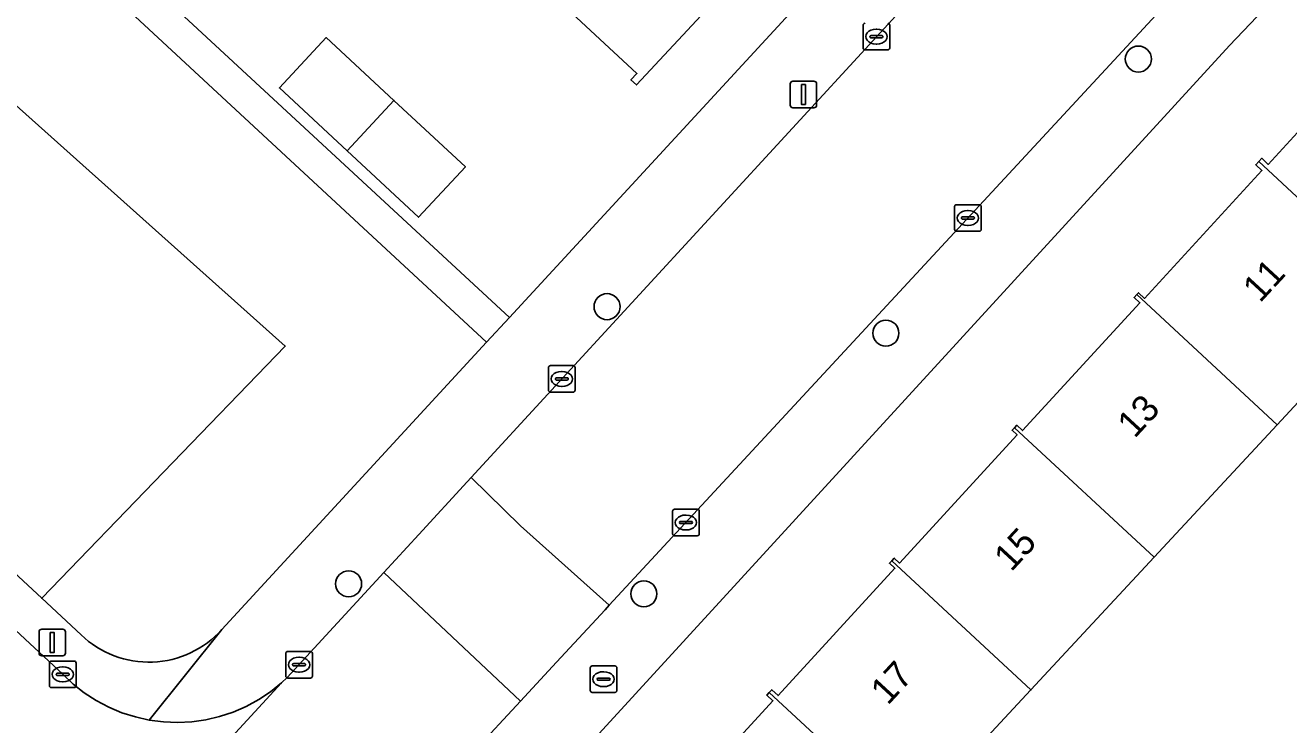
# Model space of a CAD drawing. Extents: x 159217 to 160349, y 381246 to 382172.
# Drawn here: x 159886.39 to 159933.87, y 381674.16 to 381700.45 of the extents above; entities that cross this region are included whole.
import ezdxf

# ---------------------------------------------------------------- set-up
doc = ezdxf.new("R2010")
doc.units = 0
for name, color, linetype in [('IMGEO_Boom', 7, 'Continuous'), ('IMGEO_Brandkraan', 7, 'Continuous'), ('IMGEO_Erf', 7, 'Continuous'), ('IMGEO_Groenvoorziening', 7, 'Continuous'), ('IMGEO_Kolk', 7, 'Continuous'), ('IMGEO_Lichtmast', 7, 'Continuous'), ('IMGEO_Pand', 7, 'Continuous'), ('IMGEO_Pand_nummerreeks', 7, 'Continuous'), ('IMGEO_Rijbaan_lokaal_open', 7, 'Continuous'), ('IMGEO_Voetpad_open', 7, 'Continuous')]:
    doc.layers.add(name, color=color, linetype=linetype)

msp = doc.modelspace()

# ---------------------------------------------------------------- linework, layer by layer
at = {"layer": 'IMGEO_Boom'}
for centre in [(159928.216, 381699.184), (159908.251, 381689.874), (159918.73, 381688.877), (159898.542, 381679.454), (159909.636, 381679.078)]:
    msp.add_circle(centre, 0.489, dxfattribs=at)
at = {"layer": 'IMGEO_Brandkraan'}
for p, q in [((159907.621, 381675.443), (159907.621, 381676.295)), ((159907.696, 381676.369), (159908.548, 381676.369)), ((159908.109, 381676.149), (159908.134, 381676.149)), ((159908.622, 381676.295), (159908.622, 381675.443)), ((159907.88, 381675.863), (159907.88, 381675.875)), ((159908.318, 381675.826), (159907.92, 381675.826)), ((159907.923, 381675.912), (159908.321, 381675.912)), ((159908.364, 381675.875), (159908.364, 381675.863)), ((159908.548, 381675.369), (159907.696, 381675.369)), ((159908.132, 381675.589), (159908.107, 381675.589))]:
    msp.add_line(p, q, dxfattribs=at)
for points in [[(159907.621, 381675.443), (159907.621, 381676.295)], [(159907.696, 381676.369), (159908.548, 381676.369)], [(159908.622, 381676.295), (159908.622, 381675.443)], [(159908.548, 381675.369), (159907.696, 381675.369)]]:
    msp.add_lwpolyline(points, dxfattribs=at)
for centre, radius, start, end in [((159907.698, 381676.293), 0.0765, 91.552, 178.448), ((159907.698, 381676.293), 0.0765, 91.552, 178.448), ((159908.546, 381676.293), 0.0765, 1.552, 88.448), ((159908.546, 381676.293), 0.0765, 1.552, 88.448), ((159907.92, 381675.872), 0.0403, 85.8775, 175.7526), ((159907.917, 381675.862), 0.0366, 178.938, 274.7102), ((159908.321, 381675.869), 0.043, 264.8664, 352.4533), ((159908.325, 381675.874), 0.0386, 1.7309, 96.639), ((159907.698, 381675.445), 0.0765, 181.552, 268.448), ((159907.698, 381675.445), 0.0765, 181.552, 268.448), ((159908.546, 381675.445), 0.0765, 271.552, 358.448), ((159908.546, 381675.445), 0.0765, 271.552, 358.448)]:
    msp.add_arc(centre, radius, start, end, dxfattribs=at)
for centre, major_axis, ratio, start_param, end_param in [((159908.108, 381675.869), (-0.387, 0.002), 0.722429, 4.712389, 7.853982), ((159908.133, 381675.869), (-0.39, 0.002), 0.717154, 1.570796, 4.712389)]:
    msp.add_ellipse(centre, major_axis=major_axis, ratio=ratio, start_param=start_param, end_param=end_param, dxfattribs=at)
at = {"layer": 'IMGEO_Erf'}
for points in [[(159847.871, 381715.151), (159862.984, 381701.234), (159876.444, 381715.527), (159904.584, 381689.472), (159917.923, 381703.96), (159873.098, 381745.66)], [(159955.211, 381724.431), (159931.645, 381699.69), (159903.156, 381668.59)], [(159910.098, 381670.269), (159914.487, 381675.06), (159914.255, 381675.272), (159914.347, 381675.373), (159914.439, 381675.474), (159914.68, 381675.253), (159919.066, 381680.041), (159918.863, 381680.227), (159918.951, 381680.323), (159919.041, 381680.421), (159919.244, 381680.235), (159923.662, 381685.057), (159923.474, 381685.229), (159923.56, 381685.322), (159923.645, 381685.415), (159923.866, 381685.212), (159928.274, 381690.024), (159928.057, 381690.222), (159928.155, 381690.33), (159928.217, 381690.398), (159928.45, 381690.187), (159932.857, 381694.998), (159932.628, 381695.208), (159932.74, 381695.33), (159932.852, 381695.452), (159933.1, 381695.225), (159937.498, 381700.026)], [(159938.045, 381690.407), (159933.431, 381685.435), (159928.807, 381680.452), (159924.182, 381675.468), (159919.583, 381670.513)]]:
    msp.add_lwpolyline(points, dxfattribs=at)
for points in [[(159904.989, 381702.728), (159900.602, 381706.809), (159896.139, 381710.961), (159891.711, 381715.08), (159887.361, 381719.127), (159883.151, 381723.044), (159882.945, 381722.822), (159882.765, 381722.99), (159884.38, 381724.726), (159887.785, 381728.386), (159887.946, 381728.236), (159887.703, 381727.975), (159891.932, 381724.04), (159896.283, 381719.994), (159900.711, 381715.874), (159905.173, 381711.722), (159909.56, 381707.641), (159913.942, 381703.565), (159914.075, 381703.708), (159914.398, 381703.634), (159909.356, 381698.214), (159909.152, 381698.404), (159909.377, 381698.646), (159905.716, 381702.051)], [(159897.7, 381699.993), (159900.243, 381697.627), (159902.928, 381695.129), (159901.167, 381693.236), (159898.482, 381695.734), (159895.939, 381698.1)]]:
    msp.add_lwpolyline(points, close=True, dxfattribs=at)
at = {"layer": 'IMGEO_Groenvoorziening'}
for points in [[(159903.728, 381688.543), (159877.305, 381713.035), (159875.829, 381712.89), (159864.051, 381700.243), (159868.505, 381696.104), (159876.898, 381705.634), (159896.16, 381688.389), (159887.008, 381678.914), (159888.492, 381677.536)], [(159893.779, 381677.737), (159903.728, 381688.543)]]:
    msp.add_lwpolyline(points, dxfattribs=at)
msp.add_lwpolyline([(159876.898, 381705.634), (159868.505, 381696.104), (159887.008, 381678.914), (159896.16, 381688.389)], close=True, dxfattribs=at)
msp.add_arc((159891.039, 381680.178), 3.67, 226.0485, 318.3059, dxfattribs=at)
at = {"layer": 'IMGEO_Kolk'}
for p, q in [((159917.873, 381699.602), (159917.873, 381700.454)), ((159918.874, 381700.454), (159918.874, 381699.602)), ((159918.132, 381700.022), (159918.132, 381700.034)), ((159918.57, 381699.985), (159918.172, 381699.985)), ((159918.175, 381700.071), (159918.573, 381700.071)), ((159918.361, 381700.308), (159918.386, 381700.308)), ((159918.616, 381700.034), (159918.616, 381700.022)), ((159918.8, 381699.528), (159917.948, 381699.528)), ((159918.384, 381699.748), (159918.359, 381699.748)), ((159921.387, 381693.708), (159922.239, 381693.708)), ((159921.312, 381692.782), (159921.312, 381693.634)), ((159921.614, 381693.251), (159922.012, 381693.251)), ((159921.8, 381693.488), (159921.825, 381693.488)), ((159922.313, 381693.634), (159922.313, 381692.782)), ((159921.571, 381693.202), (159921.571, 381693.214)), ((159922.009, 381693.165), (159921.611, 381693.165)), ((159921.823, 381692.928), (159921.798, 381692.928)), ((159922.055, 381693.214), (159922.055, 381693.202)), ((159922.239, 381692.708), (159921.387, 381692.708)), ((159906.051, 381686.732), (159906.051, 381687.584)), ((159906.126, 381687.658), (159906.978, 381687.658)), ((159907.052, 381687.584), (159907.052, 381686.732)), ((159906.31, 381687.152), (159906.31, 381687.164)), ((159906.748, 381687.115), (159906.35, 381687.115)), ((159906.353, 381687.201), (159906.751, 381687.201)), ((159906.539, 381687.438), (159906.564, 381687.438)), ((159906.794, 381687.164), (159906.794, 381687.152)), ((159906.978, 381686.658), (159906.126, 381686.658)), ((159906.562, 381686.878), (159906.537, 381686.878)), ((159910.717, 381681.333), (159910.717, 381682.185)), ((159910.792, 381682.259), (159911.644, 381682.259)), ((159911.205, 381682.039), (159911.23, 381682.039)), ((159911.718, 381682.185), (159911.718, 381681.333)), ((159910.976, 381681.753), (159910.976, 381681.765)), ((159911.414, 381681.716), (159911.016, 381681.716)), ((159911.019, 381681.802), (159911.417, 381681.802)), ((159911.228, 381681.479), (159911.203, 381681.479)), ((159911.46, 381681.765), (159911.46, 381681.753)), ((159911.644, 381681.259), (159910.792, 381681.259)), ((159896.179, 381675.986), (159896.179, 381676.838)), ((159896.254, 381676.912), (159897.106, 381676.912)), ((159896.667, 381676.692), (159896.692, 381676.692)), ((159897.18, 381676.838), (159897.18, 381675.986)), ((159887.299, 381675.624), (159887.299, 381676.476)), ((159887.374, 381676.55), (159888.226, 381676.55)), ((159887.787, 381676.33), (159887.812, 381676.33)), ((159888.3, 381676.476), (159888.3, 381675.624)), ((159896.438, 381676.406), (159896.438, 381676.418)), ((159896.876, 381676.369), (159896.478, 381676.369)), ((159896.481, 381676.455), (159896.879, 381676.455)), ((159896.69, 381676.132), (159896.665, 381676.132)), ((159896.922, 381676.418), (159896.922, 381676.406)), ((159887.558, 381676.044), (159887.558, 381676.056)), ((159887.996, 381676.007), (159887.598, 381676.007)), ((159887.601, 381676.093), (159887.999, 381676.093)), ((159887.81, 381675.77), (159887.785, 381675.77)), ((159888.042, 381676.056), (159888.042, 381676.044)), ((159897.106, 381675.912), (159896.254, 381675.912)), ((159888.226, 381675.55), (159887.374, 381675.55))]:
    msp.add_line(p, q, dxfattribs=at)
for points in [[(159917.873, 381699.602), (159917.873, 381700.454)], [(159918.874, 381700.454), (159918.874, 381699.602)], [(159918.8, 381699.528), (159917.948, 381699.528)], [(159921.387, 381693.708), (159922.239, 381693.708)], [(159921.312, 381692.782), (159921.312, 381693.634)], [(159922.313, 381693.634), (159922.313, 381692.782)], [(159922.239, 381692.708), (159921.387, 381692.708)], [(159906.051, 381686.732), (159906.051, 381687.584)], [(159906.126, 381687.658), (159906.978, 381687.658)], [(159907.052, 381687.584), (159907.052, 381686.732)], [(159906.978, 381686.658), (159906.126, 381686.658)], [(159910.717, 381681.333), (159910.717, 381682.185)], [(159910.792, 381682.259), (159911.644, 381682.259)], [(159911.718, 381682.185), (159911.718, 381681.333)], [(159911.644, 381681.259), (159910.792, 381681.259)], [(159896.179, 381675.986), (159896.179, 381676.838)], [(159896.254, 381676.912), (159897.106, 381676.912)], [(159897.18, 381676.838), (159897.18, 381675.986)], [(159887.299, 381675.624), (159887.299, 381676.476)], [(159887.374, 381676.55), (159888.226, 381676.55)], [(159888.3, 381676.476), (159888.3, 381675.624)], [(159897.106, 381675.912), (159896.254, 381675.912)], [(159888.226, 381675.55), (159887.374, 381675.55)]]:
    msp.add_lwpolyline(points, dxfattribs=at)
for centre, radius, start, end in [((159917.95, 381700.452), 0.0765, 91.552, 178.448), ((159917.95, 381700.452), 0.0765, 91.552, 178.448), ((159918.798, 381700.452), 0.0765, 1.552, 88.448), ((159918.798, 381700.452), 0.0765, 1.552, 88.448), ((159918.172, 381700.031), 0.0403, 85.8775, 175.7526), ((159918.169, 381700.021), 0.0366, 178.938, 274.7102), ((159918.573, 381700.028), 0.043, 264.8664, 352.4533), ((159918.577, 381700.033), 0.0386, 1.7309, 96.639), ((159917.95, 381699.604), 0.0765, 181.552, 268.448), ((159917.95, 381699.604), 0.0765, 181.552, 268.448), ((159918.798, 381699.604), 0.0765, 271.552, 358.448), ((159918.798, 381699.604), 0.0765, 271.552, 358.448), ((159921.389, 381693.632), 0.0765, 91.552, 178.448), ((159921.389, 381693.632), 0.0765, 91.552, 178.448), ((159922.237, 381693.632), 0.0765, 1.552, 88.448), ((159922.237, 381693.632), 0.0765, 1.552, 88.448), ((159921.611, 381693.211), 0.0403, 85.8775, 175.7526), ((159922.016, 381693.213), 0.0386, 1.7309, 96.639), ((159921.389, 381692.784), 0.0765, 181.552, 268.448), ((159921.389, 381692.784), 0.0765, 181.552, 268.448), ((159921.608, 381693.201), 0.0366, 178.938, 274.7102), ((159922.012, 381693.208), 0.043, 264.8664, 352.4533), ((159922.237, 381692.784), 0.0765, 271.552, 358.448), ((159922.237, 381692.784), 0.0765, 271.552, 358.448), ((159906.128, 381687.582), 0.0765, 91.552, 178.448), ((159906.128, 381687.582), 0.0765, 91.552, 178.448), ((159906.976, 381687.582), 0.0765, 1.552, 88.448), ((159906.976, 381687.582), 0.0765, 1.552, 88.448), ((159906.35, 381687.161), 0.0403, 85.8775, 175.7526), ((159906.347, 381687.151), 0.0366, 178.938, 274.7102), ((159906.751, 381687.158), 0.043, 264.8664, 352.4533), ((159906.755, 381687.163), 0.0386, 1.7309, 96.639), ((159906.128, 381686.734), 0.0765, 181.552, 268.448), ((159906.128, 381686.734), 0.0765, 181.552, 268.448), ((159906.976, 381686.734), 0.0765, 271.552, 358.448), ((159906.976, 381686.734), 0.0765, 271.552, 358.448), ((159910.794, 381682.183), 0.0765, 91.552, 178.448), ((159910.794, 381682.183), 0.0765, 91.552, 178.448), ((159911.642, 381682.183), 0.0765, 1.552, 88.448), ((159911.642, 381682.183), 0.0765, 1.552, 88.448), ((159911.016, 381681.762), 0.0403, 85.8775, 175.7526), ((159911.013, 381681.752), 0.0366, 178.938, 274.7102), ((159911.417, 381681.759), 0.043, 264.8664, 352.4533), ((159911.421, 381681.764), 0.0386, 1.7309, 96.639), ((159910.794, 381681.335), 0.0765, 181.552, 268.448), ((159910.794, 381681.335), 0.0765, 181.552, 268.448), ((159911.642, 381681.335), 0.0765, 271.552, 358.448), ((159911.642, 381681.335), 0.0765, 271.552, 358.448), ((159896.256, 381676.836), 0.0765, 91.552, 178.448), ((159896.256, 381676.836), 0.0765, 91.552, 178.448), ((159897.104, 381676.836), 0.0765, 1.552, 88.448), ((159897.104, 381676.836), 0.0765, 1.552, 88.448), ((159887.376, 381676.474), 0.0765, 91.552, 178.448), ((159887.376, 381676.474), 0.0765, 91.552, 178.448), ((159888.224, 381676.474), 0.0765, 1.552, 88.448), ((159888.224, 381676.474), 0.0765, 1.552, 88.448), ((159896.478, 381676.415), 0.0403, 85.8775, 175.7526), ((159896.475, 381676.405), 0.0366, 178.938, 274.7102), ((159896.879, 381676.412), 0.043, 264.8664, 352.4533), ((159896.883, 381676.417), 0.0386, 1.7309, 96.639), ((159887.598, 381676.053), 0.0403, 85.8775, 175.7526), ((159887.595, 381676.043), 0.0366, 178.938, 274.7102), ((159887.999, 381676.05), 0.043, 264.8664, 352.4533), ((159888.003, 381676.055), 0.0386, 1.7309, 96.639), ((159896.256, 381675.988), 0.0765, 181.552, 268.448), ((159896.256, 381675.988), 0.0765, 181.552, 268.448), ((159897.104, 381675.988), 0.0765, 271.552, 358.448), ((159897.104, 381675.988), 0.0765, 271.552, 358.448), ((159887.376, 381675.626), 0.0765, 181.552, 268.448), ((159887.376, 381675.626), 0.0765, 181.552, 268.448), ((159888.224, 381675.626), 0.0765, 271.552, 358.448), ((159888.224, 381675.626), 0.0765, 271.552, 358.448)]:
    msp.add_arc(centre, radius, start, end, dxfattribs=at)
for centre, major_axis, ratio, start_param, end_param in [((159918.36, 381700.028), (-0.387, 0.002), 0.722429, 4.712389, 7.853982), ((159918.385, 381700.028), (-0.39, 0.002), 0.717154, 1.570796, 4.712389), ((159921.799, 381693.208), (-0.387, 0.002), 0.722429, 4.712389, 7.853982), ((159921.824, 381693.208), (-0.39, 0.002), 0.717154, 1.570796, 4.712389), ((159906.538, 381687.158), (-0.387, 0.002), 0.722429, 4.712389, 7.853982), ((159906.563, 381687.158), (-0.39, 0.002), 0.717154, 1.570796, 4.712389), ((159911.204, 381681.759), (-0.387, 0.002), 0.722429, 4.712389, 7.853982), ((159911.229, 381681.759), (-0.39, 0.002), 0.717154, 1.570796, 4.712389), ((159896.666, 381676.412), (-0.387, 0.002), 0.722429, 4.712389, 7.853982), ((159896.691, 381676.412), (-0.39, 0.002), 0.717154, 1.570796, 4.712389), ((159887.786, 381676.05), (-0.387, 0.002), 0.722429, 4.712389, 7.853982), ((159887.811, 381676.05), (-0.39, 0.002), 0.717154, 1.570796, 4.712389)]:
    msp.add_ellipse(centre, major_axis=major_axis, ratio=ratio, start_param=start_param, end_param=end_param, dxfattribs=at)
at = {"layer": 'IMGEO_Lichtmast'}
for p, q in [((159915.136, 381697.45), (159915.136, 381698.25)), ((159915.136, 381698.25), (159915.136, 381697.45)), ((159915.236, 381698.35), (159916.026, 381698.35)), ((159916.026, 381698.35), (159915.236, 381698.35)), ((159916.126, 381698.25), (159916.126, 381697.45)), ((159916.126, 381697.45), (159916.126, 381698.25)), ((159916.026, 381697.35), (159915.236, 381697.35)), ((159915.236, 381697.35), (159916.026, 381697.35)), ((159886.91, 381676.848), (159886.91, 381677.648)), ((159886.91, 381677.648), (159886.91, 381676.848)), ((159887.01, 381677.748), (159887.8, 381677.748)), ((159887.8, 381677.748), (159887.01, 381677.748)), ((159887.9, 381677.648), (159887.9, 381676.848)), ((159887.9, 381676.848), (159887.9, 381677.648)), ((159887.8, 381676.748), (159887.01, 381676.748)), ((159887.01, 381676.748), (159887.8, 381676.748))]:
    msp.add_line(p, q, dxfattribs=at)
for points in [[(159915.556, 381698.225), (159915.706, 381698.225), (159915.706, 381697.475), (159915.556, 381697.475), (159915.556, 381698.225)], [(159887.33, 381677.623), (159887.48, 381677.623), (159887.48, 381676.873), (159887.33, 381676.873), (159887.33, 381677.623)]]:
    msp.add_lwpolyline(points, dxfattribs=at)
for centre, start, end in [((159915.236, 381698.25), 90, 180), ((159915.236, 381698.25), 90, 180), ((159916.026, 381698.25), 0, 90), ((159916.026, 381698.25), 360, 90), ((159915.236, 381697.45), 180, 270), ((159915.236, 381697.45), 180, 270), ((159916.026, 381697.45), 270, 0), ((159916.026, 381697.45), 270, 0), ((159887.01, 381677.648), 90, 180), ((159887.01, 381677.648), 90, 180), ((159887.8, 381677.648), 0, 90), ((159887.8, 381677.648), 360, 90), ((159887.01, 381676.848), 180, 270), ((159887.01, 381676.848), 180, 270), ((159887.8, 381676.848), 270, 0), ((159887.8, 381676.848), 270, 0)]:
    msp.add_arc(centre, 0.1, start, end, dxfattribs=at)
at = {"layer": 'IMGEO_Pand'}
for points in [[(159904.989, 381702.728), (159905.716, 381702.051), (159909.377, 381698.646), (159909.152, 381698.404), (159909.356, 381698.214), (159914.398, 381703.634), (159914.075, 381703.708), (159913.942, 381703.565), (159909.56, 381707.641)], [(159898.482, 381695.734), (159900.243, 381697.627), (159897.7, 381699.993), (159895.939, 381698.1)], [(159942.694, 381695.417), (159937.398, 381700.332), (159937.291, 381700.216), (159937.498, 381700.026), (159933.1, 381695.225), (159932.852, 381695.452), (159932.74, 381695.33), (159938.045, 381690.407)], [(159898.482, 381695.734), (159901.167, 381693.236), (159902.928, 381695.129), (159900.243, 381697.627)], [(159938.045, 381690.407), (159932.74, 381695.33), (159932.628, 381695.208), (159932.857, 381694.998), (159928.45, 381690.187), (159928.217, 381690.398), (159928.155, 381690.33), (159933.431, 381685.435)], [(159928.807, 381680.452), (159933.431, 381685.435), (159928.155, 381690.33), (159928.057, 381690.222), (159928.274, 381690.024), (159923.866, 381685.212), (159923.645, 381685.415), (159923.56, 381685.322)], [(159928.807, 381680.452), (159923.56, 381685.322), (159923.474, 381685.229), (159923.662, 381685.057), (159919.244, 381680.235), (159919.041, 381680.421), (159918.951, 381680.323), (159924.182, 381675.468)], [(159919.583, 381670.513), (159924.182, 381675.468), (159918.951, 381680.323), (159918.863, 381680.227), (159919.066, 381680.041), (159914.68, 381675.253), (159914.439, 381675.474), (159914.347, 381675.373)], [(159909.772, 381670.41), (159914.992, 381665.565), (159919.583, 381670.513), (159914.347, 381675.373), (159914.255, 381675.272), (159914.487, 381675.06), (159910.098, 381670.269), (159909.85, 381670.496)]]:
    msp.add_lwpolyline(points, close=True, dxfattribs=at)
at = {"layer": 'IMGEO_Rijbaan_lokaal_open'}
for points in [[(159943.501, 381716.626), (159938.487, 381721.428), (159934.749, 381717.486), (159931.987, 381714.619), (159927.295, 381709.736), (159903.152, 381683.456), (159904.997, 381681.639), (159908.335, 381678.645), (159935.838, 381708.361)], [(159884.832, 381663.574), (159896.024, 381675.732), (159895.608, 381675.398), (159895.163, 381675.102), (159894.694, 381674.846), (159894.204, 381674.634), (159893.696, 381674.467), (159893.176, 381674.345), (159892.647, 381674.271), (159892.114, 381674.243), (159891.58, 381674.264), (159891.05, 381674.332), (159890.529, 381674.448), (159890.02, 381674.609), (159889.527, 381674.816), (159889.055, 381675.065), (159888.607, 381675.356), (159888.186, 381675.685), (159887.797, 381676.051), (159849.425, 381711.746)], [(159838.508, 381602.939), (159860.89, 381627.268), (159889.697, 381658.416), (159901.473, 381671.232), (159904.994, 381675.037), (159899.862, 381679.876), (159896.235, 381675.927), (159896.024, 381675.732), (159884.832, 381663.574), (159884.507, 381663.136), (159872.787, 381650.412), (159870.779, 381648.232), (159867.597, 381644.778), (159865.477, 381642.489), (159862.906, 381639.713), (159853.087, 381629.109), (159835.145, 381609.655)]]:
    msp.add_lwpolyline(points, dxfattribs=at)
msp.add_lwpolyline([(159899.862, 381679.876), (159904.994, 381675.037), (159906.356, 381676.508), (159908.184, 381678.482), (159908.335, 381678.645), (159904.997, 381681.639), (159903.152, 381683.456), (159902.996, 381683.286), (159901.175, 381681.305)], close=True, dxfattribs=at)
at = {"layer": 'IMGEO_Voetpad_open'}
for points in [[(159903.156, 381668.59), (159931.645, 381699.69), (159955.211, 381724.431)], [(159847.09, 381717.249), (159847.097, 381717.43), (159847.127, 381717.678), (159847.179, 381717.923), (159847.252, 381718.162), (159847.346, 381718.393), (159847.461, 381718.616), (159847.595, 381718.827), (159844.822, 381716.038), (159849.425, 381711.746), (159887.797, 381676.051), (159888.186, 381675.685), (159888.607, 381675.356), (159889.055, 381675.065), (159889.527, 381674.816), (159890.02, 381674.609), (159890.529, 381674.448), (159891.05, 381674.332), (159893.779, 381677.737)], [(159917.923, 381703.96), (159904.584, 381689.472), (159903.728, 381688.543), (159893.779, 381677.737), (159891.05, 381674.332), (159891.58, 381674.264), (159892.114, 381674.243), (159892.647, 381674.271), (159893.176, 381674.345), (159893.696, 381674.467), (159894.204, 381674.634), (159894.694, 381674.846), (159895.163, 381675.102), (159895.608, 381675.398), (159896.024, 381675.732), (159896.235, 381675.927), (159899.862, 381679.876), (159901.175, 381681.305), (159902.996, 381683.286), (159903.152, 381683.456), (159927.295, 381709.736)], [(159935.838, 381708.361), (159908.335, 381678.645), (159908.184, 381678.482), (159906.356, 381676.508), (159904.994, 381675.037), (159901.473, 381671.232)], [(159888.492, 381677.536), (159887.008, 381678.914), (159868.505, 381696.104)]]:
    msp.add_lwpolyline(points, dxfattribs=at)
msp.add_lwpolyline([(159862.984, 381701.234), (159864.051, 381700.243), (159875.829, 381712.89), (159877.305, 381713.035), (159903.728, 381688.543), (159904.584, 381689.472), (159876.444, 381715.527)], close=True, dxfattribs=at)
msp.add_arc((159891.039, 381680.178), 3.67, 226.0485, 318.3059, dxfattribs=at)

# ---------------------------------------------------------------- texts
at = {"layer": 'IMGEO_Pand_nummerreeks'}
for s, rotation, p in [('11', 47.2518, (159932.787, 381689.99)), ('13', 47.2496, (159928.073, 381684.891)), ('15', 47.2496, (159923.438, 381679.876)), ('17', 47.2496, (159918.802, 381674.861))]:
    msp.add_text(s, height=1, rotation=rotation, dxfattribs=at).set_placement(p)

doc.saveas('drawing.dxf')
